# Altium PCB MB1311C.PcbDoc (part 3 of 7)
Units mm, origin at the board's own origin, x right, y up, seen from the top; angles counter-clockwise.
Board outline 100.03 x 67.03 mm, 6 copper layers (Top Layer, layer2, layer3, layer4, layer5, Bottom Layer), stack 1.208 mm thick; 366 components, 356 nets, 1582 pads, 964 vias.
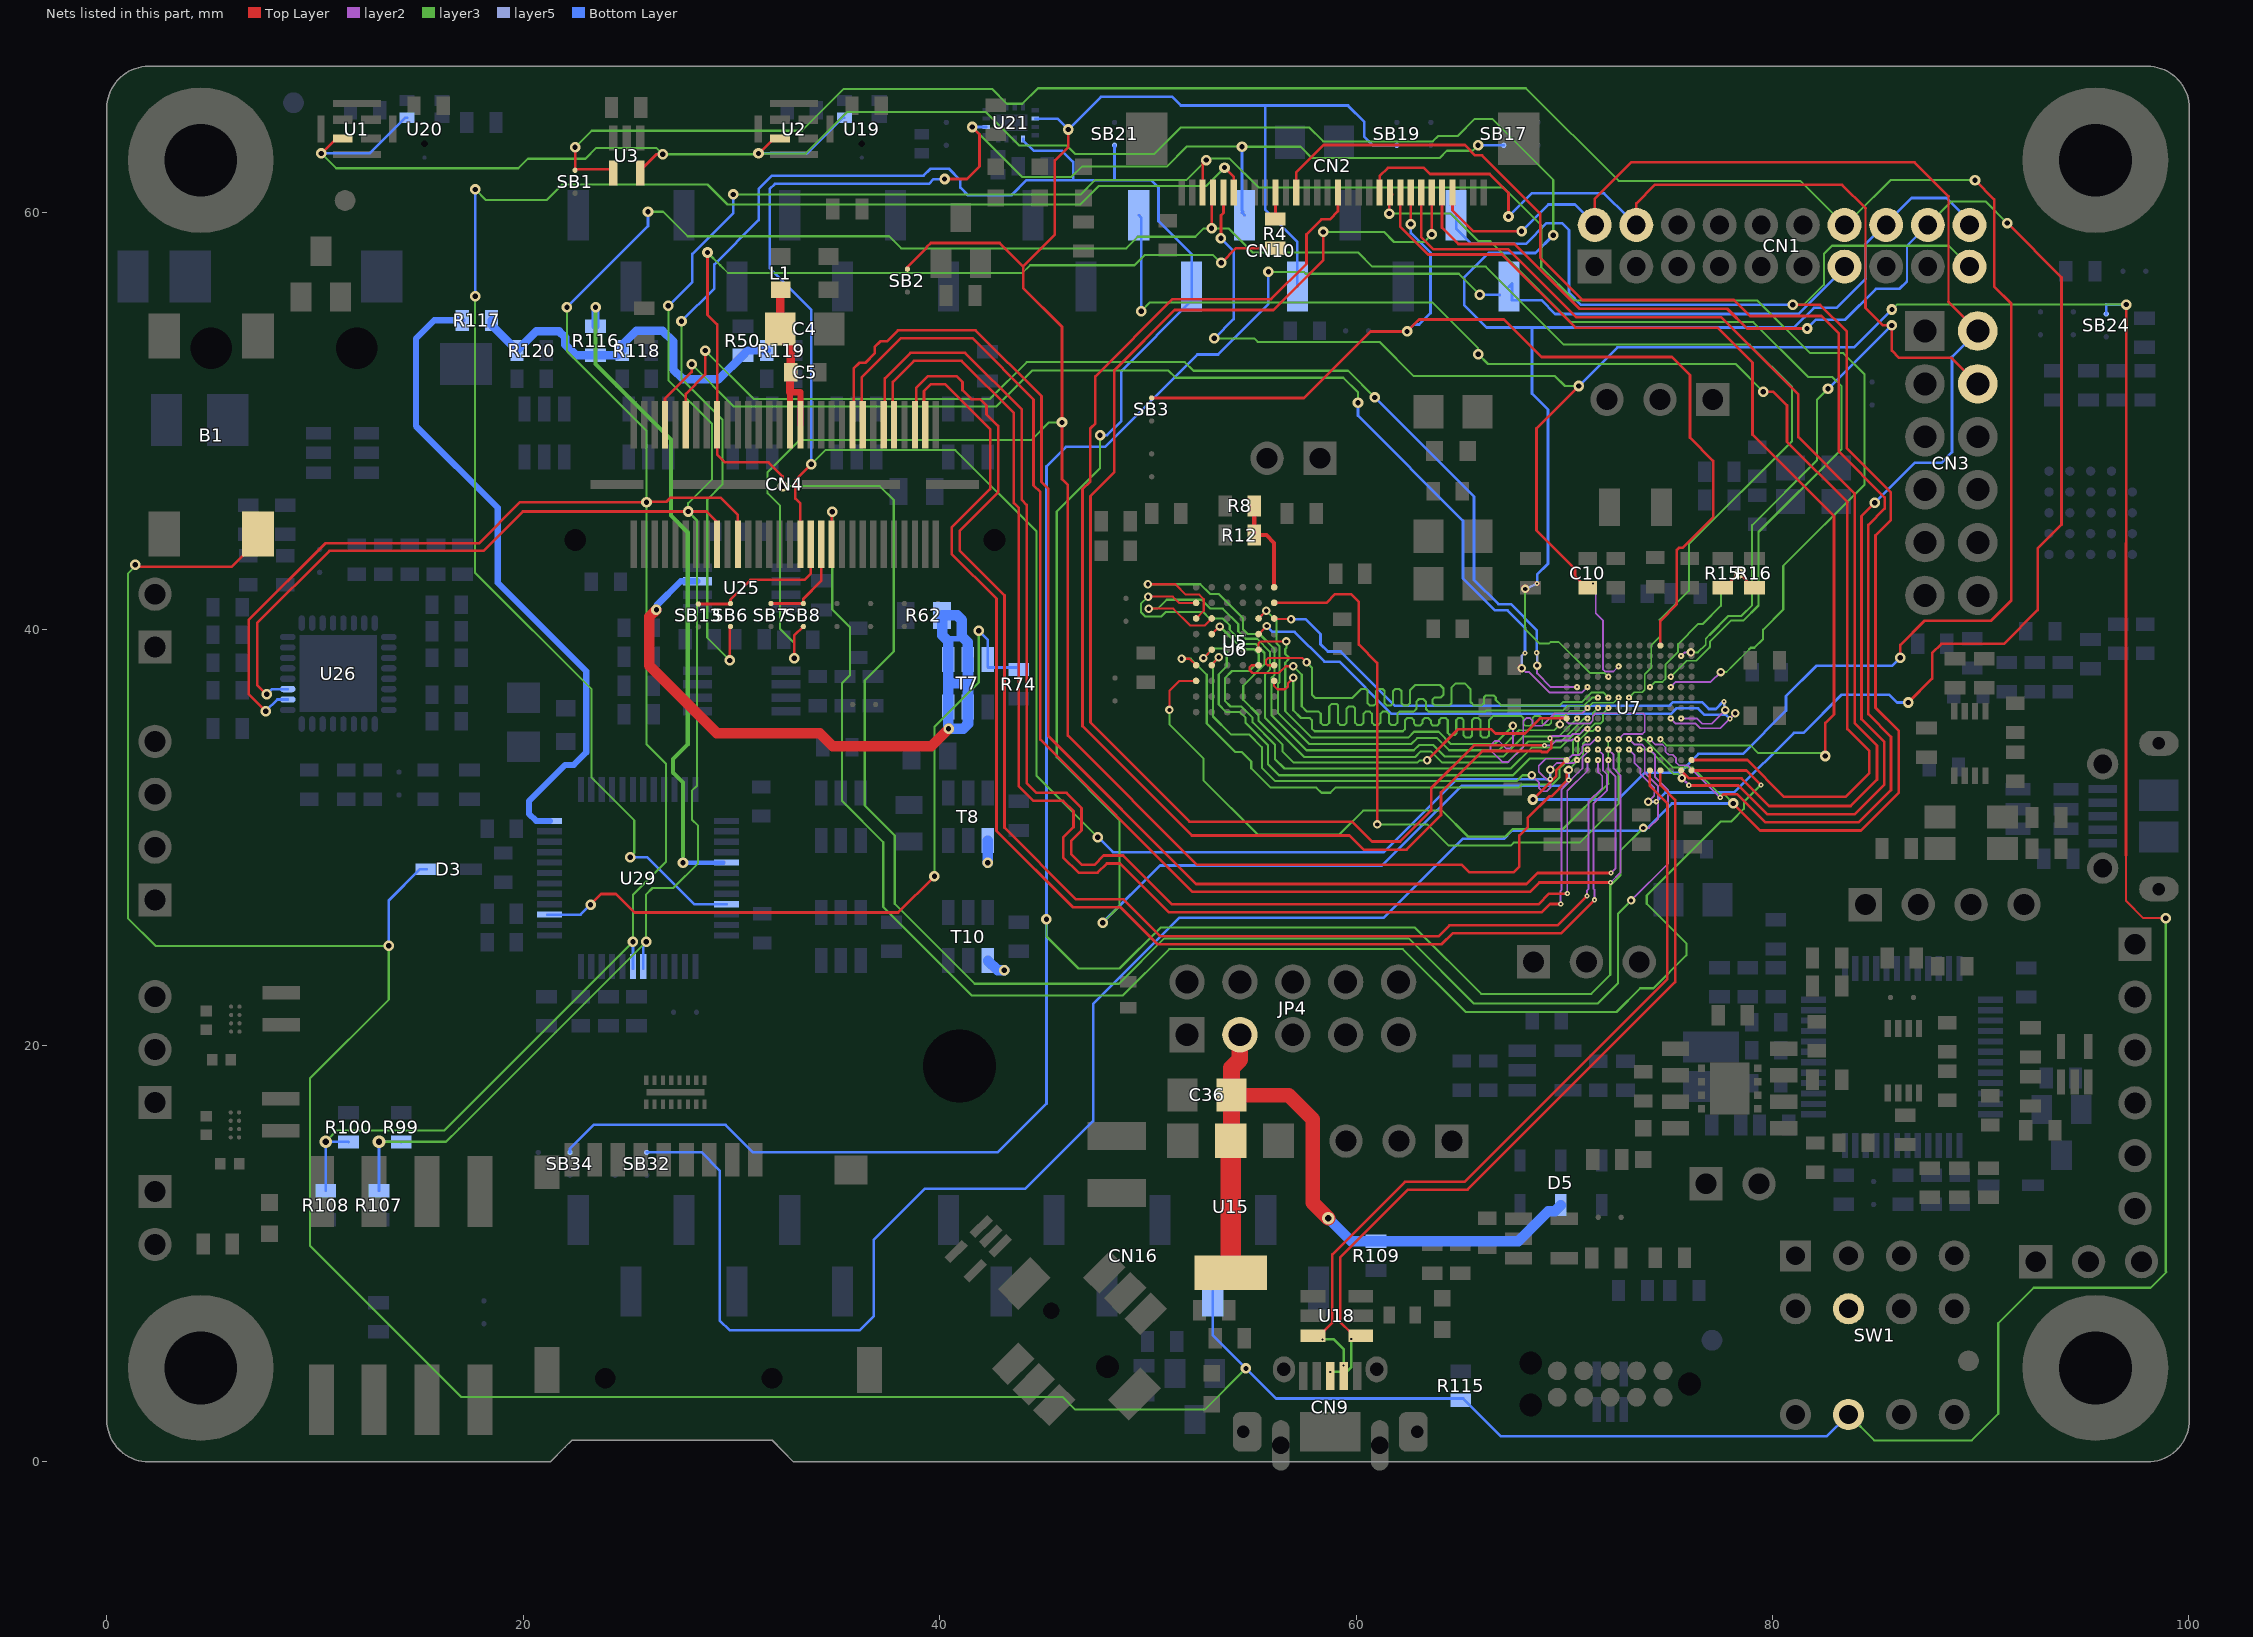
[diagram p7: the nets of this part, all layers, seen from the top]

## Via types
v1: diameter 0.508, hole 0.254, Top Layer to Bottom Layer, tented both sides, 462 vias
v2: diameter 0.61, hole 0.305, Top Layer to Bottom Layer, tented both sides, 126 vias
v3: diameter 0.406, hole 0.203, layer2 to layer5, tented both sides, 109 vias
v4: diameter 0.25, hole 0.1, Top Layer to layer2, tented both sides, 80 vias
v5: diameter 0.25, hole 0.1, Top Layer to layer3, tented both sides, 78 vias
v6: diameter 0.25, hole 0.1, layer5 to Bottom Layer, tented both sides, 52 vias
v7: diameter 0.406, hole 0.203, Top Layer to Bottom Layer, tented both sides, 48 vias
v8: diameter 0.508, hole 0.254, layer2 to layer5, tented both sides, 4 vias
v9: diameter 0.406, hole 0.203, layer2 to layer5, 3 vias
v10: diameter 0.25, hole 0.1, layer5 to Bottom Layer, tented bottom, 1 vias
v11: diameter 0.25, hole 0.1, Top Layer to layer3, tented top, 1 vias

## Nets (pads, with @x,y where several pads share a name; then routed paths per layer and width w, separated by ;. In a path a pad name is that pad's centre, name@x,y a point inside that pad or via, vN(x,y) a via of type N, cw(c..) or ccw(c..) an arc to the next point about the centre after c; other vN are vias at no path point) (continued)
ARD_D10: CN10.3 U7.A12 | length 67.1
  Top Layer w0.127: U7.A12@76.117,33.708 78.797,33.708 80.563,31.942 83.507,31.942 84.65,33.085 84.65,34.135 83.598,35.188 83.598,46.091 80.698,48.991 80.698,50.744 80.047,51.395 v1(79.563,51.395)
  layer3 w0.102: v1(49.683,55.263) 50.108,55.688 63.662,55.688 65.866,53.484 v1(65.866,53.196) 66.336,52.726 78.232,52.726 v1(79.563,51.395)
  Bottom Layer w0.127: CN10.3@49.566,59.876 49.683,59.758 v1(49.683,55.263)
ARD_D11: CN10.4 SB6.2 SB21.1 U7.L10 U21.1 | length 121.6
  Top Layer w0.127: v1(29.92,38.492) SB6.2@29.92,40.123
  layer3 w0.088: v3(70.219,33.233) 70.896,33.91 70.896,34.487 v5(71.117,34.708)
  layer3 w0.102: v1(27.603,54.783) 27.603,52.025 29.575,50.053 29.575,46.95 28.839,46.214 28.839,39.588 29.92,38.507 v1(29.92,38.492) ; v1(47.706,49.312) 47.706,47.726 45.628,45.648 45.628,33.841 48.638,30.831 48.638,26.698 v1(47.833,25.893)
  layer5 w0.127: v6(70.216,32.751) 70.213,32.754 70.219,32.761 v3(70.219,33.233)
  Bottom Layer w0.127: v1(27.603,54.783) 29.183,56.363 29.183,57.513 31.313,59.643 31.313,61.143 31.949,61.779 39.238,61.779 39.566,62.107 40.44,62.107 41,61.547 41,61.208 41.374,60.834 43.46,60.834 44.183,61.557 46.413,61.557 ; U21.1@44.013,63.538 44.013,63.473 44.523,62.963 45.883,62.963 46.413,62.433 46.413,61.557 ; v1(47.706,49.312) 48.042,49.312 48.729,49.999 48.729,52.399 52.106,55.776 CN10.4@52.106,56.447 52.106,58.002 50.515,59.593 50.515,61.204 50.162,61.557 48.413,61.557 ; v1(47.833,25.893) 50.585,28.645 61.248,28.645 65.075,32.472 69.936,32.472 v6(70.216,32.751) ; SB21.1@48.403,63.233 48.403,61.567 48.413,61.557 ; 46.413,61.557 48.413,61.557
ARD_D12: CN4.28 CN10.5 SB17.1 U7.M12 U21.6 | length 116.6
  Top Layer w0.127: CN4.28@33.313,44.073 33.313,46.03 33.072,46.271 33.072,47.152 v1(33.833,47.913) ; v1(40.239,61.616) 41.316,61.616 41.913,62.213 41.913,63.763 v1(41.563,64.113)
  layer2 w0.088: v3(69.327,33.246) 69.653,33.572 70.481,33.572 v4(70.617,33.708)
  layer3 w0.102: v1(33.833,47.913) 34.513,48.593 40.755,48.593 44.653,44.695 44.653,32.955 v1(47.602,30.006) ; v1(41.563,64.113) 43.968,61.708 46.331,61.708 46.831,62.208 50.908,62.208 51.884,63.184 54.502,63.184 v1(54.523,63.163) 57.34,63.163 57.888,62.616 64.009,62.616 64.365,62.972 65.602,62.972 v1(65.863,63.233)
  layer5 w0.127: v6(69.327,32.789) v3(69.327,33.246)
  Bottom Layer w0.127: v1(33.833,47.913) 33.833,55.343 31.838,57.338 31.838,61.138 32.085,61.385 39.482,61.385 39.705,61.608 v1@40.239,61.608 ; v1(41.563,64.113) U21.6@42.238,64.113 ; v1(47.602,30.006) 48.328,29.28 61.333,29.28 64.842,32.789 v6(69.327,32.789) v6@69.334,32.789 ; v1(54.523,63.163) 54.523,60.098 54.573,60.048 54.523,59.998 CN10.5@54.646,59.876 ; v1(65.863,63.233) SB17.1@67.093,63.233
ARD_D13: CN10.6 SB2.2 SB8.2 SB19.1 U7.N13 U21.14 | length 122.9
  Top Layer w0.127: v1(33.013,38.593) 33.013,39.682 SB8.2@33.454,40.123 ; SB2.2@38.453,57.283 38.453,57.383 39.379,58.309 39.379,58.339 39.578,58.538 42.888,58.538 44.013,57.413 ; v1(46.185,63.991) 46.185,63.16 45.537,62.512 45.537,58.937 44.013,57.413 ; U7.N13@70.117,33.208 70.117,32.704 69.381,31.968 69.281,31.968 68.249,30.936 68.249,30.496 67.844,30.091 67.844,28.592 67.565,28.313 65.442,28.313 65.082,28.673 52.364,28.673 46.159,34.878 46.159,46.916 45.878,47.197 v1(45.878,49.923) 45.878,54.518 44.013,56.383 44.013,57.413
  layer3 w0.102: v1(33.013,38.593) 33.013,39.329 32.338,40.004 32.338,45.928 31.743,46.523 31.743,47.543 33.273,49.073 44.403,49.073 45.253,49.923 v1(45.878,49.923)
  Bottom Layer w0.127: U21.14@44.588,64.513 45.663,64.513 v1(46.185,63.991) 47.751,65.557 51.176,65.557 51.59,65.143 55.633,65.143 ; CN10.6@57.186,56.447 57.186,58.6 55.633,60.153 55.633,65.143 ; SB19.1@61.963,63.233 60.813,63.233 60.403,63.643 60.403,64.353 59.623,65.133 59.623,65.143 55.633,65.143
ARD_D14: CN1.10 CN10.9 SB32.1 U7.F10 | length 149.7
  Top Layer w0.127: v1(78.113,31.623) 79.409,30.327 84.257,30.327 86.069,32.139 86.069,35.097 84.947,36.219 84.947,44.497 85.689,45.239 85.689,46.561 83.563,48.687 83.563,54.304 82.294,55.573 v1(80.978,55.573)
  layer3 w0.088: v5(73.617,34.708) 73.868,34.708 75.235,33.341
  layer3 w0.102: 75.235,33.341 76.18,33.341 77.464,32.057 77.679,32.057 v1(78.113,31.623) ; v1(80.978,55.573) 81.509,55.573 82.469,56.533 82.469,58.013 82.864,58.408 88.462,58.408 CN1.10@89.463,57.407
  Bottom Layer w0.127: SB32.1@25.933,14.863 25.943,14.873 28.553,14.873 29.438,13.988 29.438,6.798 29.923,6.313 36.153,6.313 36.833,6.993 36.833,10.663 39.279,13.109 44.109,13.109 47.373,16.373 47.373,21.995 51.514,26.136 61.336,26.136 65.122,29.922 67.096,29.922 67.479,30.305 73.852,30.305 75.17,31.623 v1(78.113,31.623) ; CN10.9@64.806,59.875 64.806,59.24 65.547,58.498 68.158,58.498 69.155,59.495 69.886,59.495 70.227,59.154 70.227,56.156 70.81,55.573 v1(80.978,55.573)
ARD_D15: CN1.7 CN10.10 SB34.1 U7.G10 | length 145.6
  layer2 w0.088: v5(73.117,34.708) 73.367,34.458 73.72,34.458 73.866,34.311 73.866,33.101 74.511,32.456 74.511,30.891 74.067,30.447 v9(73.799,30.447)
  layer3 w0.102: v1(45.132,26.064) 45.132,25.23 46.669,23.693 48.643,23.693 50.61,25.66 62.83,25.66 66.013,22.477 71.302,22.477 72.213,23.388 72.213,27.679 72.697,28.163 72.697,29.345 v9(73.799,30.447) ; v1(55.793,57.153) 57.49,57.153 57.578,57.065 64.933,57.065 v1(65.948,56.05)
  Bottom Layer w0.127: SB34.1@22.247,14.863 22.247,15.047 23.383,16.183 29.718,16.183 31.039,14.862 42.792,14.862 45.132,17.202 v1(45.132,26.064) 45.132,47.811 46.07,48.749 47.947,48.749 52.382,53.184 53.376,53.184 55.793,55.601 v1(55.793,57.153) ; v1(65.948,56.05) 66.896,56.05 CN10.10@66.903,56.043 ; CN1.7@83.463,57.813 CN1.7@83.463,57.407 83.463,57.335 81.257,55.129 69.568,55.129 68.904,55.793 67.492,55.793 67.492,56.593 CN10.10@67.353,56.454 ; CN10.10@67.353,56.454 CN10.10@67.346,56.447 67.353,56.447 CN10.10@67.353,56.454
BLGND: C4.2 C5.2 CN4.27 CN4.29 L1.2 | length 8.7
  Top Layer w0.3: CN4.29@32.813,49.813 32.813,51.353 ; 32.813,51.373 33.313,51.373 CN4.27@33.313,49.813
  Top Layer w0.4: C4.2@32.208,54.303 32.843,53.668 C5.2@32.843,52.333 32.813,52.303 32.813,51.373 ; C4.2@32.348,54.413 32.348,56.268 L1.2@32.373,56.293
BOOT0: R15.2 R16.2 U7.E5 | length 9.8
  Top Layer w0.127: R15.2@77.61,41.923 77.635,41.923 v1(78.397,42.685) 79.134,41.948 R16.2@79.134,41.923
  layer3 w0.088: v5(74.117,37.208) 74.369,37.46 74.511,37.46 74.513,37.458 74.72,37.458 74.867,37.606 74.867,38.311 75.468,38.912 75.468,39.279 76.439,40.25
  layer3 w0.102: 76.439,40.25 76.663,40.25 77.523,41.111 77.523,41.811 v1(78.397,42.685)
CAL: R74.1 T7.3 U29.3 | length 36.2
  Top Layer w0.127: v1(23.235,26.763) 23.748,27.276 24.45,27.276 25.343,26.383 38.013,26.383 v1(39.753,28.123)
  layer3 w0.102: v1(39.753,28.123) 39.753,35.303 41.882,37.432 v1(41.882,39.916)
  Bottom Layer w0.127: U29.3@21.171,26.283 22.755,26.283 v1(23.235,26.763) ; v1(41.882,39.916) 41.882,39.904 42.313,39.473 T7.3@42.313,38.546 42.313,38.183 42.343,38.153 43.703,38.153 R74.1@43.803,38.053
CAL_D: R62.2 T7.1 T7.2 T7.5 T7.6 T8.4 T10.4 U25.3 | length 38.8
  Top Layer w0.508: v1(26.4,40.925) 26.059,40.584 26.059,38.247 29.306,35 34.25,35 34.875,34.375 39.593,34.375 v1(40.431,35.213)
  Bottom Layer w0.25: 40.204,39.635 40.302,39.537 41.19,39.537 41.213,39.537
  Bottom Layer w0.305: v1(26.4,40.925) 26.4,41.13 27.566,42.296 U25.3@28.368,42.296
  Bottom Layer w0.5: T10.4@42.323,24.076 42.786,23.613 v1(43.103,23.613)
  Bottom Layer w0.508: R62.2@40.118,40.652 R62.2@40.132,40.652 ; 40.204,39.635 40.13,39.709 R62.2@40.132,40.652 ; 40.302,39.537 40.411,39.428 T7.1@40.411,38.596 ; T7.1@40.411,38.397 T7.1@40.411,38.596 ; v1@40.413,35.213 40.413,37.413 ; v1(40.431,35.213) 41.128,35.213 41.363,35.448 T7.5@41.363,36.246 41.363,37.396 ; 41.073,39.689 41.073,40.422 40.843,40.652 R62.2@40.132,40.652 ; 41.075,39.652 41.19,39.537 41.361,39.366 T7.2@41.361,38.347 ; T7.2@41.363,38.546 41.363,37.396 ; v1(42.316,28.779) T8.4@42.316,29.836 ; T7.1@40.411,38.596 40.413,38.596 T7.1@40.413,38.546 40.413,37.413 ; 40.413,37.413 40.43,37.396 41.363,37.396
Camera_CLK: CN2.21 R4.1 | length 1.3
  Top Layer w0.127: R4.1@56.123,59.693 56.132,59.702 CN2.21@56.132,60.973
CKOUT: CN1.18 CN1.20 U1.3 U2.3 U3.5 U7.J4 U19.4 U20.4 | length 135.9
  Top Layer w0.127: v1(10.303,62.843) 10.323,62.843 11.043,63.563 U1.3@11.338,63.563 ; U3.5@25.683,62.083 26.403,62.803 v1(26.703,62.803) ; v1(31.303,62.843) 31.323,62.843 32.043,63.563 U2.3@32.338,63.563
  layer3 w0.088: 68.806,39.31 69.28,39.31 69.348,39.378 69.739,39.378 71.226,37.891 71.93,37.891 72.113,37.708 v5(72.117,37.708)
  layer3 w0.102: v1(10.303,62.843) 11.015,62.131 19.769,62.131 20.224,62.586 22.996,62.586 23.517,63.107 26.399,63.107 v1(26.703,62.803) 31.263,62.803 v1(31.303,62.843) 33.571,62.843 35.56,64.832 42.211,64.832 43.818,63.225 46.11,63.225 46.518,62.817 50.317,62.817 51.596,64.096 57.745,64.096 58.418,63.423 63.684,63.423 63.934,63.673 64.872,63.673 65.702,64.503 66.544,64.503 69.473,61.574 v1(69.473,58.913) ; v3(68.123,41.928) 68.123,39.993 68.806,39.31
  layer5 w0.127: v3(68.123,41.928) v6(68.699,42.18)
  Bottom Layer w0.102: 84.47,56.823 84.47,58.493
  Bottom Layer w0.127: v1(10.303,62.843) 12.623,62.843 14.335,64.555 U20.4@14.425,64.555 ; v1(31.303,62.843) 33.623,62.843 35.335,64.555 U19.4@35.425,64.555 ; v6(68.699,42.18) 68.699,42.613 69.221,43.135 69.221,50.533 68.453,51.301 68.453,54.483 ; v1(69.473,58.913) 68.623,58.063 66.374,58.063 65.194,56.883 65.194,55.562 66.273,54.483 68.453,54.483 ; 84.47,56.823 83.07,55.423 81.987,55.423 81.047,54.483 68.453,54.483 ; 84.47,58.493 86.68,60.703 88.353,60.703 89.243,59.813 CN1.20@89.463,59.813
CRE_CS2: R8.1 R12.2 U5.A6 U6.A6 | length 4.6
  Top Layer w0.2: R8.1@55.113,45.913 R12.2@55.113,44.513 55.694,44.513 56.069,44.138 U5.A6@56.069,42.008
D0: U5.B6 U6.B6 U7.H11 | length 30.9
  Top Layer w0.127: U5.B6@56.069,41.258 58.577,41.258 58.991,41.672 59.764,41.672 60.136,41.3 60.136,39.25 61.017,38.369 v7(61.017,30.618)
  layer3 w0.102: v7(61.017,30.618) 63.422,30.618 64.445,29.595 67.433,29.595 67.576,29.738 70.743,29.738 72.617,31.612 v5(72.617,34.208)
D1: U5.C5 U6.C5 U7.H10 | length 27.9
  Top Layer w0.102: U5.C5@55.319,40.508 v7(55.69,40.879)
  layer2 w0.088: v3(69.795,35.415) 69.795,35.707 69.866,35.778 70.064,35.778 70.138,35.704 70.138,35.533 70.213,35.458 71.22,35.458 71.367,35.606 71.367,35.811 71.513,35.957 72.067,35.957 ; 72.066,35.958 72.067,35.957 ; v5(72.617,34.708) 72.87,34.961 73.758,34.961 73.864,35.067 73.864,35.862 73.769,35.957 72.067,35.957
  layer3 w0.088: 67.827,35.137 69.517,35.137 v3(69.795,35.415)
  layer3 w0.102: v7(55.69,40.879) 56.172,40.396 56.172,39.332 56.321,39.184 56.321,37.433 56.249,37.361 56.249,35.978 57.746,34.481 62.657,34.481 62.936,34.76 63.894,34.76 64.478,34.176 66.866,34.176 67.425,34.735 67.827,35.137
D2: U5.C6 U6.C6 U7.B8 | length 26.9
  Top Layer w0.102: U5.C6@56.069,40.508 56.102,40.475 v7(56.884,40.475)
  layer2 w0.088: v4(75.617,35.708) 76.375,35.708 76.631,35.452 77.086,35.452 77.737,36.103 v3(77.737,36.109)
  layer5 w0.127: v6(77.669,36.511) v3(77.737,36.109)
  Bottom Layer w0.127: v7(56.884,40.475) 57.569,40.475 58.293,39.751 58.293,39.269 58.644,38.918 59.259,38.918 61.868,36.31 75.045,36.31 75.222,36.487 76.619,36.487 76.95,36.157 77.284,36.157 77.638,36.511 v6(77.669,36.511)
D3: U5.D5 U6.D5 U7.C8 | length 28.8
  Top Layer w0.102: U5.D5@55.319,39.758 55.328,39.758 v7(55.715,40.145)
  layer2 w0.088: v4(75.117,35.708) 75.366,35.458 76.315,35.458 76.535,35.238 77.504,35.238 v3(78.22,35.954)
  layer5 w0.127: v6(77.96,35.692) 77.96,35.694 v3(78.22,35.954)
  Bottom Layer w0.127: v7(55.715,40.145) 55.997,39.863 57.045,39.863 58.478,38.43 59.208,38.43 61.71,35.929 75.121,35.929 75.38,36.188 76.436,36.188 76.744,35.88 77.772,35.88 v6(77.96,35.692)
D4: U5.E5 U6.E5 U7.L7 | length 27
  Top Layer w0.102: U5.E5@55.319,39.008 55.319,39.321 55.401,39.403 v7(56.653,39.403)
  layer2 w0.088: v3(67.538,35.358) 67.538,34.428 67.372,34.262 67.225,34.262 66.866,34.621 66.661,34.621 66.462,34.422 66.462,34.166 67.013,33.615 67.324,33.615 68.032,34.323 68.032,35.578 68.173,35.719 68.357,35.719 68.479,35.597 68.479,35.432 68.553,35.358 68.949,35.358 69.549,35.958 70.867,35.958 v4(71.117,36.208)
  layer3 w0.102: v7(56.653,39.403) 56.653,39.088 56.602,39.037 56.602,38.807 56.648,38.761 56.651,38.761 56.754,38.658 56.754,38.54 56.602,38.388 56.602,36.058 57.874,34.786 62.506,34.786 62.785,35.065 63.967,35.065 64.553,34.479 66.66,34.479 v3(67.538,35.358)
D5: U5.F5 U6.F5 U7.K6 | length 26.9
  Top Layer w0.102: U5.F5@55.319,38.258 54.983,38.258 54.886,38.161 54.886,38.032 55.031,37.887 56.292,37.887 56.618,38.213 v7(56.983,38.213)
  layer3 w0.088: 69.937,36.084 70.17,36.317 70.948,36.317 71.339,36.708 v5(71.617,36.708)
  layer3 w0.102: v7(56.983,38.213) 56.987,38.213 57.392,37.808 57.392,36.284 57.646,36.03 58.206,36.03 58.308,35.929 58.308,35.497 58.41,35.395 58.613,35.395 58.714,35.497 58.714,36.285 58.836,36.407 59.061,36.407 59.143,36.325 59.143,36.25 59.143,35.497 59.245,35.395 59.448,35.395 59.549,35.497 59.549,36.18 59.645,36.276 59.86,36.276 59.956,36.18 59.956,35.497 60.057,35.395 60.261,35.395 60.362,35.497 60.362,35.929 60.464,36.03 60.667,36.03 60.769,35.929 60.769,35.497 60.87,35.395 61.073,35.395 61.175,35.497 61.175,35.929 61.277,36.03 61.48,36.03 61.581,35.929 61.581,35.497 61.683,35.395 61.886,35.395 61.988,35.497 61.988,35.929 62.089,36.03 62.77,36.03 62.897,36.157 62.897,36.513 63.024,36.64 63.234,36.64 63.361,36.513 63.361,36.157 63.488,36.03 66.198,36.03 66.249,36.081 69.934,36.081 69.937,36.084
D6: U5.F6 U6.F6 U7.J6 | length 27.3
  Top Layer w0.102: U5.F6@56.069,38.258 55.756,38.258 55.675,38.339 55.675,38.505 55.774,38.604 57.431,38.604 v7(57.627,38.408)
  layer3 w0.088: 69.795,36.335 69.957,36.497 70.857,36.497 71.318,36.958 71.867,36.958 v5(72.117,36.708)
  layer3 w0.102: v7(57.627,38.408) 57.889,38.146 57.889,36.849 58.047,36.691 59.824,36.691 60.256,37.122 60.459,37.122 60.561,37.021 60.561,36.437 60.662,36.335 60.865,36.335 60.967,36.437 60.967,37.021 61.069,37.122 61.272,37.122 61.373,37.021 61.373,36.437 61.475,36.335 61.678,36.335 61.78,36.437 61.78,37.021 61.881,37.122 62.085,37.122 62.186,37.021 62.186,36.437 62.288,36.335 62.491,36.335 62.593,36.437 62.593,37.053 62.851,37.311 64.034,37.311 64.199,37.146 64.199,36.838 64.081,36.72 63.778,36.72 63.665,36.607 63.665,36.448 63.778,36.335 64.485,36.335 64.595,36.445 64.595,37.199 64.784,37.388 65.222,37.388 65.496,37.114 65.496,36.492 65.653,36.335 66.031,36.335 66.145,36.449 66.145,36.711 66.239,36.805 66.622,36.805 66.71,36.717 66.71,36.593 66.968,36.335 69.795,36.335
D7: U5.G6 U6.G6 U7.H6 | length 27.3
  Top Layer w0.102: U5.G6@56.069,37.508 56.069,37.257 56.221,37.105 56.595,37.105 56.73,37.24 56.73,37.401 v7(56.985,37.656)
  layer3 w0.088: 68.047,35.717 68.047,35.436 68.127,35.356 68.369,35.356 68.474,35.461 68.474,35.708 68.593,35.827 68.826,35.827 68.948,35.705 68.948,35.462 69.026,35.384 69.256,35.384 69.378,35.506 69.375,35.509 69.375,35.683 69.38,35.683 69.524,35.827 70.027,35.827 70.276,36.076 70.98,36.076 71.362,36.458 72.366,36.458 v5(72.617,36.708)
  layer3 w0.102: v7(56.985,37.656) 56.985,36.099 57.359,35.725 57.781,35.725 57.882,35.624 57.882,35.217 58.009,35.09 62.251,35.09 62.353,35.192 62.353,35.624 62.454,35.725 62.678,35.725 62.779,35.624 62.779,35.471 62.881,35.37 63.084,35.37 63.186,35.471 63.186,35.606 63.305,35.725 63.473,35.725 63.592,35.606 63.592,35.471 63.694,35.37 63.897,35.37 63.999,35.471 63.999,35.624 64.1,35.725 64.303,35.725 64.405,35.624 64.405,35.016 64.511,34.91 64.737,34.91 64.811,34.984 64.811,35.624 64.913,35.725 65.065,35.725 65.167,35.624 65.167,34.887 65.268,34.786 65.471,34.786 65.573,34.887 65.573,35.624 65.675,35.725 65.878,35.725 65.979,35.624 65.979,34.887 66.081,34.786 66.284,34.786 66.386,34.887 66.386,35.624 66.487,35.725 66.589,35.827 67.937,35.827 68.047,35.717
D8: U5.B1 U6.B1 U7.N8 | length 31.2
  Top Layer w0.102: v7(50.013,41.555) 51.204,41.555 51.501,41.258 U5.B1@52.319,41.258
  Top Layer w0.127: v7(63.411,33.695) 63.413,33.695 64.91,35.192 66.487,35.192 66.697,34.982 68.109,34.982 68.834,35.708 U7.N8@70.117,35.708
  layer3 w0.102: v7(50.013,41.555) 49.665,41.207 49.665,40.82 49.888,40.597 50.634,40.597 50.857,40.82 52.658,40.82 52.977,40.501 53.612,40.501 53.937,40.176 53.937,39.973 54.629,39.281 55.176,39.281 55.606,38.851 55.606,38.304 54.585,37.283 54.585,36.605 55.318,35.872 55.318,35.603 56.476,34.445 56.476,34.112 57.003,33.585 62.947,33.585 63.057,33.695 v7(63.411,33.695)
D9: U5.C1 U6.C1 U7.M8 | length 31.4
  Top Layer w0.102: v7(50.007,42.148) 51.329,42.148 51.826,41.651 52.469,41.651 52.684,41.436 52.684,40.873 U5.C1@52.319,40.508
  layer3 w0.088: 68.036,34.838 69.747,34.838 v5(70.617,35.708)
  layer3 w0.102: v7(50.007,42.148) 52.526,42.148 52.987,41.687 53.396,41.687 54.572,40.511 54.572,39.985 54.795,39.761 55.362,39.761 56.092,39.031 56.092,37.797 55.944,37.649 55.944,35.851 57.619,34.176 62.776,34.176 63.03,34.43 63.717,34.43 64.276,33.871 67.069,33.871 68.036,34.838
D10: U5.C2 U6.C2 U7.L8 | length 31.5
  Top Layer w0.102: v7(50.042,40.978) 51.227,40.978 52.035,40.17 52.731,40.17 U5.C2@53.069,40.508
  layer3 w0.088: 68.284,34.604 69.866,34.604 70.969,35.708 v5(71.117,35.708)
  layer3 w0.102: v7(50.042,40.978) 50.479,40.978 50.907,41.406 52.58,41.406 53.008,40.978 53.604,40.978 54.344,40.238 54.344,39.89 54.701,39.533 55.248,39.533 55.864,38.917 55.864,38.049 55.62,37.805 55.62,35.754 57.517,33.857 62.848,33.857 63.117,34.126 63.59,34.126 64.133,33.583 67.263,33.583 68.284,34.604
D11: U5.D2 U6.D2 U7.K7 | length 27.6
  Top Layer w0.102: U5.D2@53.069,39.758 53.429,40.119 v7(53.455,40.119)
  layer3 w0.088: 68.441,34.303 69.819,34.303 70.975,35.458 71.005,35.458 ; 71.013,35.458 71.22,35.458 71.366,35.605 71.366,35.958 v5(71.617,36.208)
  layer3 w0.102: v7(53.455,40.119) 53.468,40.119 54.56,39.027 55.097,39.027 55.328,38.796 55.328,38.43 54.88,37.982 54.045,37.982 53.702,37.639 53.702,36.549 53.972,36.279 54.492,36.279 55.035,35.736 55.035,35.523 56.105,34.453 56.105,33.76 56.564,33.301 57.412,33.301 67.438,33.301 68.441,34.303
D12: U5.E2 U6.E2 U7.J7 | length 27.3
  Top Layer w0.102: v7(52.673,38.603) v7(52.673,38.603) 53.074,39.002 53.074,39.003 U5.E2@53.069,39.008
  layer3 w0.088: 69.773,33.783 70.222,33.783 70.414,33.975 70.414,34.612 71.08,35.278 71.295,35.278 71.475,35.458 71.72,35.458 71.866,35.605 71.866,35.957 v5(72.117,36.208)
  layer3 w0.102: v7(52.673,38.603) 53.143,39.073 53.603,39.073 53.792,38.884 53.792,38.207 53.409,37.824 53.409,36.373 53.771,36.011 54.419,36.011 54.696,35.734 54.696,35.485 55.77,34.411 55.77,33.509 56.304,32.975 57.339,32.975 67.542,32.975 68.35,33.783 69.773,33.783
D13: U5.F2 U6.F2 U7.K10 | length 27
  Top Layer w0.102: U5.F2@53.069,38.258 53.069,38.299 53.403,38.633 v7(53.403,38.643)
  layer2 w0.088: v3(68.436,32.979) 68.781,32.634 68.781,32.372 68.942,32.211 69.156,32.211 69.346,32.401 69.346,32.586 68.779,33.153 68.779,33.429 69.118,33.768 70.226,33.768 70.415,33.957 70.719,33.957 70.867,34.106 70.867,34.339 70.986,34.458 71.243,34.458 71.493,34.708 v5(71.617,34.708)
  layer3 w0.102: v7(53.403,38.643) 53.129,38.369 53.129,36.862 53.129,35.802 53.988,34.943 54.861,34.943 55.479,34.325 55.479,33.333 56.117,32.695 57.296,32.695 67.71,32.695 67.994,32.979 v3(68.436,32.979)
D14: U5.F1 U6.F1 U7.K9 | length 26.9
  Top Layer w0.102: v7(51.624,38.571) 52.006,38.571 U5.F1@52.319,38.258
  layer3 w0.088: 69.77,32.875 69.77,33.285 70.044,33.559 70.084,33.559 ; 70.084,33.559 70.26,33.559 70.661,33.96 70.661,34.605 71.154,35.098 71.369,35.098 71.479,35.208 v5(71.617,35.208)
  layer3 w0.102: v7(51.624,38.571) 52.061,38.571 52.83,37.802 52.83,35.463 54.198,34.095 54.515,34.095 54.969,33.641 54.969,33.313 55.901,32.381 58.096,32.381 58.34,32.137 58.765,32.137 59.009,32.381 67.817,32.381 67.971,32.535 69.43,32.535 69.77,32.875
D15: U5.G1 U6.G1 U7.J10 | length 31.1
  Top Layer w0.102: v7(51.037,36.112) 51.037,37.022 51.523,37.508 U5.G1@52.319,37.508
  layer3 w0.088: 72.117,32.572 v5(72.117,34.708)
  layer3 w0.102: v7(51.037,36.112) 51.037,35.42 52.669,33.788 52.669,32.74 55.276,30.133 59.2,30.133 60.347,31.28 64.135,31.28 65.377,30.038 67.178,30.038 67.533,30.393 69.938,30.393 72.117,32.572
D_N: CN9.2 U7.E13 U18.3 | length 38.7
  Top Layer w0.122: v5(58.386,5.885) 58.386,6.222 58.862,6.697 58.862,9.961 62.349,13.449 65.205,13.449 74.951,23.195 74.951,31.631 74.893,31.689 74.117,32.466 U7.E13@74.117,33.208 ; v5(59.409,4.635) 59.409,4.182 59.378,4.151 CN9.2@59.413,4.118 CN9.2@59.413,4.118
  layer3 w0.122: v5(58.386,5.885) 58.934,5.885 59.409,5.411 v5(59.409,4.635)
D_P: CN9.3 U7.D13 U18.4 | length 38.8
  Top Layer w0.122: CN9.3@58.763,4.118 58.739,4.142 58.764,4.166 v5(58.764,4.319) ; v5(59.772,5.902) 59.772,6.179 59.237,6.713 59.237,9.806 62.505,13.073 65.361,13.073 75.327,23.039 75.327,31.793 ; U7.D13@74.617,33.208 74.617,32.504 75.328,31.793
  layer3 w0.122: v5(58.764,4.319) 59.549,4.319 59.765,4.535 59.765,5.902 v5(59.772,5.902)
DATIN1: CN1.17 SB1.2 U3.4 U7.N12 | length 127.3
  Top Layer w0.127: v1(22.493,63.133) SB1.2@22.493,62.033 22.543,62.083 U3.4@24.383,62.083 ; v1(68.497,31.813) 69.609,32.925 69.609,33.2 U7.N12@70.117,33.708 ; v1(86.143,38.623) 86.143,39.243 87.298,40.398 90.509,40.398 91.47,41.359 91.47,55.626 90.651,56.445 90.651,60.638 v1(89.73,61.559)
  layer3 w0.102: v1(22.493,63.133) 23.293,63.933 33.378,63.933 35.388,65.943 42.514,65.943 43.23,65.227 43.976,65.227 44.724,65.975 68.159,65.975 72.612,61.522 81.339,61.522 82.988,59.873 CN1.17@83.523,59.873 ; CN1.17@82.905,59.813 CN1.17@83.463,59.813 ; v1(89.73,61.559) 85.669,61.559 83.983,59.873 CN1.17@83.523,59.873 ; CN1.17@83.463,59.813 CN1.17@83.523,59.873 ; CN1.17@83.463,59.813 83.584,59.813 CN1.17@83.523,59.873
  Bottom Layer w0.127: v1(68.497,31.813) 72.585,31.813 73.861,33.089 75.529,33.089 76.449,34.009 78.58,34.009 80.652,36.081 80.652,36.781 82.104,38.233 85.753,38.233 v1(86.143,38.623)
DCMI_CLK: CN4.43 R4.2 U7.E11 | length 120.1
  Top Layer w0.127: v1(28.853,58.083) 28.853,55.083 29.313,54.623 CN4.43@29.313,49.813 29.313,48.373 29.683,48.003 31.783,48.003 32.463,47.323 v1(32.463,46.863) ; v1(53.531,57.59) 54.234,58.293 R4.2@56.123,58.293
  layer2 w0.088: v9(73.213,26.963) 74.988,28.738 74.988,32.266 74.366,32.888 74.366,33.959 v4(74.117,34.208)
  layer3 w0.089: 29.465,57.471 29.836,57.1 43.979,57.1 44.35,57.471
  layer3 w0.102: v1(28.853,58.083) 29.465,57.471 ; v1(32.463,46.863) 37.133,46.863 37.796,46.2 37.796,38.921 36.403,37.528 36.403,31.523 37.843,30.083 37.843,26.803 41.683,22.963 48.613,22.963 50.793,25.143 62.527,25.143 65.658,22.012 71.604,22.012 72.59,22.998 72.59,26.34 v9(73.213,26.963) ; 44.35,57.471 49.364,57.471 49.866,57.973 53.123,57.973 53.506,57.59 v1(53.531,57.59)
DCMI_D0: CN1.11 CN2.4 CN3.7 U7.F11 | length 74.2
  Top Layer w0.102: 88.456,55.715 88.456,60.78
  Top Layer w0.127: CN2.4@64.632,60.973 64.632,60.108 65.637,59.103 v1(67.953,59.103) ; CN1.11@71.463,59.813 71.463,60.662 73.214,62.413 86.823,62.413 88.456,60.78 ; v4(75.984,32.498) 75.984,32.487 78.369,32.487 79.756,31.101 83.938,31.101 85.373,32.536 85.373,34.573 84.275,35.671 84.275,45.43 v1(84.909,46.064) ; 88.456,55.715 89.468,54.703 CN3.7@90.053,54.703
  layer2 w0.127: v3(75.653,32.841) 75.653,32.828 v4(75.984,32.498)
  layer3 w0.088: v5(73.617,34.208) 74.077,34.208 75.254,33.031 75.463,33.031 v3(75.653,32.841)
  Bottom Layer w0.127: v1(67.953,59.103) 69.237,60.387 70.51,60.387 71.084,59.813 CN1.11@71.463,59.813 ; v1(84.909,46.064) 86.827,47.982 88.109,47.982 88.622,48.495 88.622,53.069 CN3.7@89.866,54.313
DCMI_D1: CN1.19 CN2.5 U7.G11 | length 81.5
  Top Layer w0.102: CN1.19@87.463,59.763 CN1.19@87.463,59.813
  Top Layer w0.127: CN2.5@64.132,60.973 64.132,59.274 64.913,58.493 67.613,58.493 70.723,55.383 77.83,55.383 78.778,54.435 v1(81.663,54.435) ; v1(86.523,36.473) 87.669,37.619 87.669,38.841 88.117,39.289 91.119,39.289 92.74,40.91 92.74,43.87 93.884,45.014 93.884,56.892 v1(91.279,59.497)
  layer2 w0.088: v4(73.117,34.208) 73.367,33.957 73.367,33.584 73.653,33.298 73.653,33.042 74.323,32.372 74.323,31.983 v3(74.04,31.7)
  layer3 w0.102: CN1.19@87.463,59.813 87.871,59.813 88.594,60.536 90.24,60.536 v1(91.279,59.497)
  layer5 w0.127: v3(74.04,31.7) v6(74.422,31.707)
  Bottom Layer w0.102: 86.456,56.702 86.456,58.4 CN1.19@87.463,59.407
  Bottom Layer w0.127: v6(74.422,31.707) 74.861,32.146 78.16,32.146 81.03,35.016 81.496,35.016 83.329,36.849 85.607,36.849 85.983,36.473 v1(86.523,36.473) ; v1(81.663,54.435) 82.075,54.847 83.473,54.847 84.963,56.337 86.091,56.337 86.456,56.702
DCMI_D2: CN2.6 U7.M10 | length 67
  Top Layer w0.127: v1(58.433,59.073) 58.433,57.719 56.037,55.323 51.283,55.323 48.389,52.429 48.389,47.533 47.248,46.392 47.248,35.507 52.003,30.752 59.812,30.752 60.772,29.792 62.117,29.792 63.605,31.28 63.605,32.353 65.664,34.412 v4(69.052,34.412) ; CN2.6@63.632,60.973 63.683,60.922 63.623,60.862 63.633,60.852 v1(63.633,58.953)
  layer2 w0.088: v4(69.052,34.412) 69.377,34.412 69.606,34.641 70.351,34.641 70.418,34.708 v4(70.617,34.708)
  layer3 w0.102: v1(58.433,59.073) 61.344,59.073 61.826,58.591 63.271,58.591 v1(63.633,58.953)
DCMI_D3: CN2.7 U7.B13 | length 54.1
  Top Layer w0.127: CN2.7@63.132,60.973 63.132,58.826 63.718,58.239 67.316,58.239 70.572,54.983 77.521,54.983 81.241,51.263 81.241,49.212 83.946,46.507 83.946,35.48 85.023,34.403 85.023,32.763 83.761,31.501 79.84,31.501 78.514,32.827 75.998,32.827 U7.B13@75.617,33.208
DCMI_D4: CN2.8 SB3.1 U7.D1 | length 50.8
  Top Layer w0.127: SB3.1@50.186,51.094 57.495,51.094 60.694,54.293 v1(62.453,54.293) 63.028,54.868 67.106,54.868 68.908,53.066 75.179,53.066 76.044,52.201 76.044,49.193 77.156,48.081 77.156,45.365 75.686,43.896 75.514,43.896 75.402,43.784 75.402,41.182 74.617,40.397 U7.D1@74.617,39.208 ; v1(62.632,59.449) CN2.8@62.632,60.973
  Bottom Layer w0.127: v1(62.453,54.293) 62.789,54.628 63.03,54.628 63.577,55.175 63.577,58.079 62.632,59.024 v1(62.632,59.449)
DCMI_D5: CN2.9 U7.D10 | length 50.2
  Top Layer w0.127: CN2.9@62.132,60.973 62.132,59.32 63.467,57.985 67.022,57.985 70.534,54.473 77.364,54.473 79.044,52.793 79.044,49.333 82.957,45.42 82.957,35.906 82.543,35.492 v1(82.543,33.903)
  layer3 w0.088: v5(74.617,34.708) 74.913,34.412 78.947,34.412 79.304,34.055
  layer3 w0.102: 79.304,34.055 82.391,34.055 v1(82.543,33.903)
DCMI_D6: CN2.10 U7.C4 | length 44.3
  Top Layer w0.127: v1(61.593,59.953) 61.593,60.732 61.733,60.872 CN2.10@61.632,60.973
  layer3 w0.088: v5(75.117,37.708) 75.886,38.477 76.342,38.477 76.975,39.11
  layer3 w0.102: v1(61.593,59.953) 64.56,59.953 65.883,58.63 66.454,58.63 70.342,54.742 79.087,54.742 81.724,52.105 82.879,52.105 83.321,51.663 83.321,48.649 79.333,44.661 79.333,41.129 78.607,40.403 78.004,40.403 77.007,39.406 77.007,39.142 76.975,39.11
DCMI_D7: CN1.12 CN2.11 CN3.8 U7.B2 | length 61.5
  Top Layer w0.102: 84.47,55.836 84.47,60.21
  Top Layer w0.127: CN2.11@61.132,60.973 61.132,61.754 61.526,62.148 63.257,62.148 63.552,61.853 66.418,61.853 67.323,60.948 v1(67.323,59.813) ; CN1.12@73.463,59.813 73.463,60.448 74.347,61.332 83.348,61.332 84.47,60.21 ; 84.47,55.836 84.47,55.427 85.314,54.583 v1(85.733,54.583) 85.733,53.373 86.081,53.025 88.601,53.025 89.463,52.163 CN3.8@90.053,52.163
  layer2 w0.088: v4(75.617,38.708) 75.784,38.875 v3(76.086,38.875)
  layer3 w0.088: v3(76.086,38.875) 76.421,38.875 76.8,39.254 76.8,39.538 76.975,39.713
  layer3 w0.102: 76.975,39.713 77.893,40.631 78.512,40.631 79.023,41.142 79.023,44.985 82.133,48.095 82.133,51.003 v1(82.668,51.538)
  Bottom Layer w0.127: v1(67.323,59.813) 68.438,60.928 71.921,60.928 73.036,59.813 CN1.12@73.463,59.813 ; v1(82.668,51.538) 85.713,54.583 v1(85.733,54.583)
DCMI_I2C1_SCL: CN2.28 CN4.44 R99.2 R107.1 U7.C5 U26.3 U29.42 | length 174.7
  Top Layer w0.127: v1(7.688,36.863) 7.663,36.863 7.223,37.303 7.223,40.286 10.69,43.753 18.093,43.753 19.983,45.643 v1(27.923,45.643) 28.814,45.643 29.313,45.144 CN4.44@29.313,44.073 ; CN2.28@52.632,60.973 52.632,62.352 v1(52.803,62.523)
  layer2 w0.088: v4(75.117,37.208) 75.366,37.457 77.04,37.457 77.512,37.93 v3(77.515,37.93)
  layer3 w0.088: v3(77.515,37.93) 77.52,37.935 77.795,37.935 78.124,38.264 78.124,38.268 78.874,39.018
  layer3 w0.102: v2(13.073,15.373) 16.295,15.373 16.924,16.002 v1(25.906,24.984) 25.906,27.256 26.213,27.563 27.213,27.563 28.4,28.75 28.4,30.55 28.1,30.85 28.1,32.225 28.35,32.475 28.35,45.216 v1(27.923,45.643) 27.923,46.048 29.075,47.2 29.075,49.85 26.973,51.952 v1(26.973,55.523) ; v1(30.093,60.873) 46.773,60.873 47.459,61.559 51.839,61.559 v1(52.803,62.523) 52.875,62.595 53.931,62.595 55.316,61.21 67.077,61.21 68.898,59.389 68.898,57.378 70.494,55.782 79.278,55.782 81.808,53.252 83.402,53.252 84.422,52.232 84.422,46.933 80.521,43.032 80.521,40.941 79.553,39.973 79.553,39.522 79.131,39.1 78.956,39.1 78.874,39.018
  Bottom Layer w0.127: v1(7.688,36.863) 7.938,37.113 U26.3@8.688,37.113 ; R107.1@13.073,13.023 v2(13.073,15.373) 14.133,15.373 R99.2@14.143,15.363 ; U29.42@25.771,23.683 25.771,24.849 v1(25.906,24.984) ; v1(26.973,55.523) 28.123,56.673 28.123,58.013 30.093,59.983 v1(30.093,60.873)
DCMI_I2C1_SDA: CN2.27 CN4.40 R100.2 R108.1 U7.G6 U26.2 U29.43 | length 175.9
  Top Layer w0.127: v1(7.633,36.053) 6.813,36.873 6.813,40.433 10.493,44.113 17.873,44.113 19.853,46.093 v1(25.923,46.093) 25.937,46.107 26.871,46.107 27.072,46.308 29.472,46.308 30.313,45.467 CN4.40@30.313,44.073 ; v1(53.063,59.243) 53.063,60.824 53.103,60.864 53.063,60.904 CN2.27@53.132,60.973
  layer3 w0.088: v5(73.117,36.708) 73.369,36.96 73.746,36.96 73.869,37.083 73.869,37.822 74.181,38.134 74.181,39.228 74.588,39.635 74.588,40.443
  layer3 w0.102: v2(10.513,15.373) 11.053,15.913 16.203,15.913 v1(25.271,24.981) 25.271,27.231 26.853,28.813 26.853,33.543 25.923,34.473 v1(25.923,46.093) 25.918,46.098 25.918,49.534 22.1,53.352 v1(22.1,55.46) ; v1(25.993,60.043) 26.723,60.043 27.901,58.865 37.576,58.865 38.157,58.284 48.962,58.284 49.519,58.841 52.281,58.841 52.683,59.243 v1(53.063,59.243) 53.623,59.243 53.875,59.243 55.033,58.085 60.101,58.085 60.779,57.407 66.236,57.407 69.982,53.661 78.911,53.661 80.941,51.631 80.941,49.023 75.984,44.066 75.984,41.839 74.588,40.443
  Bottom Layer w0.127: v1(7.633,36.053) 8.193,36.613 U26.2@8.693,36.613 ; R108.1@10.513,13.023 v2(10.513,15.373) 11.603,15.373 R100.2@11.613,15.363 ; v1(22.1,55.46) 25.993,59.353 v1(25.993,60.043) ; U29.43@25.271,23.683 v1(25.271,24.981)
DCMI_NRST: B1.3 C10.1 CN2.26 CN16.3 D3.2 R115.2 SB24.1 SW1.7 U7.H3 | length 284
  Top Layer w0.102: 96.982,29.134 96.982,26.944 97.813,26.113 v1@98.863,26.113
  Top Layer w0.127: v1(1.363,43.088) 1.408,43.088 1.483,43.013 1.464,42.994 6.01,42.994 7.263,44.247 B1.3@7.263,44.563 ; v1(53.513,58.763) 53.513,59.867 53.632,59.986 CN2.26@53.632,60.973 ; v1(70.702,51.673) 68.669,49.64 68.669,44.739 70.517,42.891 70.517,42.539 71.133,41.923 v4(71.387,42.177) ; 96.982,29.134 96.982,40.128 96.993,48.184 v1(96.993,55.583)
  layer2 w0.088: v4(71.387,42.177) 71.514,42.05 71.514,40.755 71.87,40.399 71.87,38.811 71.87,38.05 71.961,37.959 72.368,37.959 v4(72.617,38.208)
  layer3 w0.102: v1(1.363,43.088) 1.363,43.013 1.011,42.661 1.011,26.115 2.343,24.783 v1(13.543,24.783) 13.543,22.203 9.763,18.423 9.763,10.377 17.027,3.113 45.913,3.113 46.517,2.509 52.734,2.509 v1(54.713,4.488) ; v1(53.193,53.963) 55.111,53.963 55.282,53.792 61.126,53.792 62.77,52.148 69.56,52.148 70.035,51.673 v1(70.702,51.673) ; SW1.7@83.638,2.288 SW1.7@83.653,2.273 84.893,1.033 89.573,1.033 90.843,2.303 90.843,6.663 92.543,8.363 98.163,8.363 98.913,9.113 98.888,9.138 v1(98.888,26.113) ; v1(85.74,55.346) 85.977,55.583 v1(96.993,55.583)
  Bottom Layer w0.127: v1(13.543,24.783) 13.543,26.963 15.043,28.463 D3.2@15.363,28.463 ; CN16.3@53.122,8.186 53.122,6.079 v1(54.713,4.488) 56.156,3.045 65.147,3.045 66.97,1.221 82.601,1.221 83.618,2.238 SW1.7@83.638,2.238 ; v1(53.193,53.963) 54.122,54.892 54.122,58.154 v1(53.513,58.763) ; v1(70.702,51.673) 72.556,53.527 83.921,53.527 v1(85.74,55.346) ; SB24.1@96.033,55.133 96.033,55.583 ; v1(96.993,55.583) 96.033,55.583 ; 96.033,55.583 96.023,55.583 96.033,55.593 96.033,55.583
DCMI_PIXCLK: CN2.15 U7.L9 | length 63.9
  Top Layer w0.127: CN2.15@59.132,60.973 59.132,60.069 58.741,59.678 58.344,59.678 57.62,58.954 57.62,57.536 55.927,55.843 51.183,55.843 47.476,52.136 47.476,49.882 47.237,49.643 47.237,47.095 46.863,46.721 46.863,35.335 52.114,30.084 59.682,30.084 60.363,29.403 62.425,29.403 64.082,31.06 64.082,32.156 66.07,34.144 68.871,34.144 68.921,34.095 69.184,34.095 69.37,34.281 69.37,34.697 v4(69.312,34.755)
  layer2 w0.088: v4(69.312,34.755) 69.413,34.856 70.287,34.856 70.389,34.959 70.735,34.959 70.985,35.208 v4(71.117,35.208)
DCMI_PWR_EN: CN2.25 U29.33 | length 79.9
  Top Layer w0.127: v1(53.683,62.163) 54.132,61.714 CN2.25@54.132,60.973
  layer3 w0.102: v1(17.694,55.983) 17.694,42.692 23.285,37.101 23.285,32.861 25.335,30.811 25.335,29.235 v1(25.143,29.043) ; v1(17.694,61.114) 18.202,60.606 21.137,60.606 21.884,61.353 28.85,61.353 29.81,60.393 46.753,60.393 47.633,61.273 52.793,61.273 v1(53.683,62.163)
  Bottom Layer w0.127: v1(17.694,55.983) v1(17.694,61.114) ; v1(25.143,29.043) 25.953,29.043 28.213,26.783 U29.33@29.771,26.783
DCMI_VSYNC: CN2.19 U7.E10 | length 70.4
  Top Layer w0.127: CN2.19@57.132,60.973 57.132,61.941 58.436,63.245 65.232,63.245 65.723,62.754 66.052,62.754 68.843,59.963 68.843,57.842 70.882,55.803 78.153,55.803 78.922,55.034 82.352,55.034 83.188,54.198 83.188,48.517 85.387,46.318 85.387,45.784 84.605,45.002 84.605,35.911 85.693,34.823 85.693,32.263 84.142,30.712 79.66,30.712 78.304,32.067 77.657,32.067 v4(77.493,31.903)
  layer2 w0.088: v4(74.117,34.708) 74.37,34.455 74.719,34.455 74.864,34.31 74.864,34.112 75.014,33.961 75.218,33.961 75.364,33.815 75.364,33.797 ; 75.365,33.796 75.365,33.607 75.513,33.459 75.937,33.459 v4(77.493,31.903)
DSI_1V8_PWRON: R117.1 U29.12 | length 31.3
  Bottom Layer w0.3: R117.1@17.075,54.825 15.725,54.825 14.85,53.95 14.85,49.75 18.775,45.825 18.775,42.225 23.025,37.975 23.025,34.075 22.425,33.475 22.025,33.475 20.275,31.725 20.275,31.125 20.617,30.783 U29.12@21.271,30.783
DSI_3V3_PWRON: R116.1 U29.29 | length 31.9
  layer3 w0.2: v1(23.475,55.45) 23.475,52.725 27.1,49.1 27.1,45.45 27.9,44.65 27.9,34.45 27.2,33.75 27.2,33.1 27.675,32.625 v1(27.675,28.775)
  Bottom Layer w0.127: U29.29@29.623,28.775 U29.29@29.651,28.803
  Bottom Layer w0.2: v1(27.675,28.775) U29.29@29.623,28.775
  Bottom Layer w0.4: R116.1@23.475,54.55 v1(23.475,55.45)
DSI_BL_CTRL: CN4.53 U7.L5 | length 58.2
  Top Layer w0.127: CN4.53@26.813,49.813 26.813,51.063 28.093,52.343 v1(28.093,52.713)
  layer2 w0.088: v3(67.958,38.113) 68.14,37.931 68.314,37.931 69.286,36.959 70.867,36.959 v4(71.117,37.208)
  layer3 w0.102: v1(28.093,52.713) 30.119,50.687 42.727,50.687 44.454,52.414 50.99,52.414 51.336,52.068 59.394,52.068 60.094,51.368 v1(60.094,50.872)
  layer5 w0.127: v3(67.958,38.113) 67.958,38.693 v6(68.119,38.854)
  Bottom Layer w0.127: v1(60.094,50.872) 60.094,50.247 65.141,45.2 65.141,42.424 66.667,40.898 67.276,40.898 68.119,40.055 v6(68.119,38.854)
DSI_CK_N: CN4.5 U7.K12 | length 66.2
  Top Layer w0.127: CN4.5@38.813,49.813 38.873,49.872 38.873,51.582 39.435,52.144 40.813,52.144 41.097,51.86 41.097,51.472 41.526,51.043 41.948,51.043 42.255,50.736 42.255,50.314 42.812,49.757 42.812,46.565 40.963,44.716 40.963,43.769 43.116,41.616 43.116,30.458 46.556,27.018 48.839,27.018 50.616,25.241 63.958,25.241 64.483,25.766 69.677,25.766 v4(71.094,27.183)
  layer2 w0.088: v4(71.094,27.183) 71.094,27.439 71.161,27.506 71.161,31.696 71.828,32.363 71.828,32.94 71.617,33.151 v5(71.617,33.708)
DSI_CK_P: CN4.3 U7.K11 | length 66.4
  Top Layer w0.127: CN4.3@39.313,49.813 39.254,49.872 39.254,51.424 39.593,51.763 40.267,51.763 42.431,49.599 42.431,46.723 40.582,44.874 40.582,43.611 42.735,41.458 42.735,30.3 46.398,26.637 48.681,26.637 50.458,24.86 64.116,24.86 64.641,25.385 69.853,25.385 v4(71.461,26.993)
  layer2 w0.088: v4(71.461,26.993) 71.461,27.468 71.4,27.529 71.4,31.605 72.058,32.263 72.058,33.014 71.867,33.205 71.867,33.958 v5(71.617,34.208)
DSI_D0_N: CN4.11 U7.L12 | length 66.3
  Top Layer w0.127: CN4.11@37.313,49.813 37.373,49.872 37.373,52.032 38.605,53.264 41.22,53.264 43.948,50.536 43.948,46.201 44.184,45.965 44.184,32.604 44.659,32.129 46.093,32.129 46.815,31.407 46.815,30.324 46.319,29.828 46.319,29.192 46.834,28.677 47.434,28.677 47.878,29.121 48.816,29.121 51.157,26.78 68.767,26.78 69.278,27.291 v4(70.148,27.291)
  layer2 w0.088: v4(70.148,27.291) 70.148,32.228 71.118,33.198 v4(71.118,33.711)
DSI_D0_P: CN4.9 U7.L11 | length 66.4
  Top Layer w0.127: CN4.9@37.813,49.813 37.754,49.872 37.754,51.874 38.763,52.883 41.062,52.883 43.567,50.378 43.567,46.043 43.803,45.807 43.803,32.446 44.501,31.748 45.935,31.748 46.434,31.249 46.434,30.482 45.938,29.986 45.938,29.034 46.676,28.296 47.592,28.296 48.036,28.74 48.658,28.74 50.999,26.399 68.925,26.399 69.322,26.796 v4(69.832,26.796)
  layer2 w0.088: v4(69.832,26.796) 69.826,26.801 69.826,27.424 69.874,27.472 69.874,32.304 70.87,33.3 70.87,33.845 71.117,34.092 v4(71.117,34.208)
DSI_D1_N: CN4.17 U7.J12 | length 66.3
  Top Layer w0.127: CN4.17@35.813,49.813 35.873,49.872 35.873,52.516 36.146,52.789 36.433,52.789 36.883,53.239 36.883,53.553 37.149,53.819 37.463,53.819 37.992,54.348 41.73,54.348 44.893,51.185 44.893,47.063 45.22,46.736 45.22,34.85 52.314,27.756 68.184,27.756 68.713,28.285 v4(72.251,28.285)
  layer2 w0.088: v4(72.117,33.708) 72.117,33.266 72.455,32.928 72.455,28.489 v4(72.251,28.285)
DSI_D1_P: CN4.15 U7.J11 | length 66.4
  Top Layer w0.127: CN4.15@36.313,49.813 36.254,49.872 36.254,52.071 38.15,53.967 41.572,53.967 44.512,51.027 44.512,46.905 44.839,46.578 44.839,34.693 52.156,27.375 68.354,27.375 68.806,27.827 v4(72.223,27.827)
  layer2 w0.088: v4(72.117,34.208) 72.369,33.957 72.369,33.305 72.699,32.975 72.699,28.303 v4(72.223,27.827)
DSI_PWR_ON: R50.2 R116.2 R117.2 R118.2 R119.2 R120.2 | length 18
  Bottom Layer w0.4: R117.2@18.475,54.825 18.475,54.6 R120.2@19.7,53.375 20.625,54.3 21.725,54.3 22.025,54 22.025,53.65 22.525,53.15 R116.2@23.475,53.15 24.525,53.15 R118.2@24.75,53.375 24.75,53.65 25.425,54.325 26.7,54.325 27.2,53.825 27.2,52.475 27.675,52 29.4,52 R50.2@30.55,53.15 30.775,53.375 R119.2@31.7,53.375
DSI_SPI2_CLK: CN4.24 SB7.1 SB8.1 | length 4.8
  Top Layer w0.127: SB7.1@31.903,41.223 SB8.1@33.454,41.223 33.454,41.454 34.313,42.313 CN4.24@34.313,44.073
DSI_SPI2_MOSI: CN4.26 SB6.1 SB13.1 | length 7.5
  Top Layer w0.127: SB13.1@28.413,41.203 29.94,41.203 SB6.1@29.96,41.223 29.96,41.41 30.913,42.363 33.513,42.363 33.813,42.663 CN4.26@33.813,44.073
DSI_SPI_USART_CS: CN4.22 U7.A13 | length 80.7
  Top Layer w0.127: CN4.22@34.813,44.073 34.813,45.603 v1(34.843,45.633) ; U7.A13@76.117,33.208 78.746,33.208 v5(79.445,32.509)
  layer3 w0.102: v1(34.843,45.633) 34.843,40.936 35.695,40.084 35.695,37.776 35.31,37.391 35.31,31.746 37.293,29.763 37.293,26.646 41.537,22.402 48.802,22.402 51.026,24.626 62.252,24.626 65.27,21.608 72.508,21.608 73.648,22.748 74.288,22.748 75.865,24.325 75.865,24.904 73.966,26.803 73.966,27.201 77.528,30.763 78.032,30.763 78.629,31.36 78.629,31.693 v5(79.445,32.509)
DSI_TE: CN4.49 U7.M5 | length 57.5
  Top Layer w0.127: CN4.49@27.813,49.813 27.813,51.293 28.743,52.223 v1(28.743,53.373)
  layer2 w0.088: v3(68.698,38.243) 68.698,37.866 69.356,37.208 v4(70.617,37.208)
  layer3 w0.102: v1(28.743,53.373) 31.07,51.046 42.413,51.046 44.184,52.817 51.782,52.817 52.195,52.404 59.622,52.404 v1(60.904,51.122)
  layer5 w0.127: v6(68.676,38.86) 68.698,38.838 v3(68.698,38.243)
  Bottom Layer w0.127: v1(60.904,51.122) 65.666,46.36 65.666,42.361 66.836,41.191 67.432,41.191 68.676,39.947 v6(68.676,38.86)
E5V: C36.1 D5.1 JP4.3 R109.1 U15.2 U15.4 | length 33.4
  Top Layer w0.7: U15.2@53.983,15.428 U15.2@54.018,15.463 ; C36.1@54.018,17.623 54.038,17.603 56.762,17.603 57.913,16.452 57.913,12.453 v2(58.66,11.706)
  Top Layer w0.8: U15.2@54.018,15.463 C36.1@54.018,17.623 54.018,18.918 54.423,19.323 JP4.3@54.423,20.513
  Top Layer w1: U15.4@53.983,9.078 U15.2@53.983,15.428
  Bottom Layer w0.5: v2(58.66,11.706) 59.773,10.593 R109.1@60.963,10.593 67.799,10.593 69.242,12.036 69.536,12.036 D5.1@69.833,12.333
